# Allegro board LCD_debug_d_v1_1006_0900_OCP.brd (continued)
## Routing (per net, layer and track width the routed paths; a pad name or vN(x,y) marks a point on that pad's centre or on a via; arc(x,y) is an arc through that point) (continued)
DEBUG_V2_PRSNT: length 4.7
  TOP w0.165: v1(59.2,18.17) 57.37,18.17 R901.1 R900.2
  BOTTOM w0.165: v1(59.2,18.17) 59.03,18 U15.7
DISCHARGE_GATE: length 1.3
  TOP w0.102: Q29.G 12.43,7.65 12.82,7.26 U24.3
EEPROM_E0: length 3.8
  TOP w0.165: U16.1 60.45,5.93 60.92,5.46 R788.2 R790.2
EEPROM_E1: length 5.2
  TOP w0.165: R787.2 R791.2 58.89,6.73 59.35,7.2 U16.2
EEPROM_E2: length 6.2
  TOP w0.165: R792.1 57.18,12.73 57.18,12.09 56.98,11.89 R786.2 57.31,11.88 58.99,10.2 58.99,9.25 59.77,8.47 U16.3
FACTORY_RST: length 19.4
  TOP w0.165: R732.2 3.13,12.57 3.35,12.79 3.35,14.36 4.53,15.54 4.53,16.54 4.59,16.6 v1(4.59,16.67)
  BOTTOM w0.165: v1(4.59,16.67) 4.66,16.67 4.99,16.99 4.99,25.85 2.12,28.71 U10.22
JTAG_TI_TCK: length 39.5
  BOTTOM w0.165: J13.1 5.61,5.48 6.56,4.54 8.49,4.54 10.91,6.96 10.91,7.99 12.39,9.47 15.04,9.47 15.17,9.6 24.38,9.6 25.43,10.65 26.44,10.65 26.64,10.85 30.04,10.85 31.79,12.6 33.66,12.6 34.2,12.06 37.42,12.06 37.72,12.36 37.72,12.47 R882.1 R881.1
JTAG_TI_TCK_R: length 4.9
  TOP w0.165: U21.B15 v2(42.54,15.9)
  BOTTOM w0.165: R881.2 40.19,12.7 42.54,15.05 v2(42.54,15.9)
JTAG_TI_TDI: length 39.5
  BOTTOM w0.165: J13.2 5.28,6.49 6.75,5.01 8.29,5.01 10.44,7.16 10.44,8.19 12.2,9.94 14.85,9.94 14.99,10.08 24.2,10.08 25.23,11.12 26.24,11.12 26.44,11.32 29.84,11.32 31.59,13.07 35.43,13.07 35.57,13.21 37.44,13.21 R475.1 R474.1
JTAG_TI_TDI_R: length 6.4
  TOP w0.165: v2(42.65,17.81) 42.68,17.81 U21.D14
  BOTTOM w0.165: v2(42.65,17.81) 42.68,17.81 43.01,17.48 43.01,16.97 42.04,16 42.04,15.22 40.54,13.72 R474.2
JTAG_TI_TDO: length 47.5
  TOP w0.165: v1(5.28,4.47) 5.7,4.89 v1(5.7,7.47)
  BOTTOM w0.165: v1(5.7,7.47) 5.68,7.48 J13.3 ; v1(5.28,4.47) 5.68,4.07 8.68,4.07 11.39,6.78 11.39,7.8 12.59,9 15.23,9 15.35,9.12 24.56,9.12 25.62,10.18 26.65,10.18 26.84,10.38 30.23,10.38 31.98,12.13 33.37,12.13 33.98,11.52 38.02,11.52 38.73,12.23 40.38,12.23 42.03,13.87 R473.1
JTAG_TI_TDO_R: length 3
  TOP w0.165: U21.C14 v2(43.54,16.95)
  BOTTOM w0.165: v2(43.54,16.95) 43.54,16.38 43.09,15.93 43.09,14.7 R473.2
JTAG_TI_TMS: length 41.4
  BOTTOM w0.165: J13.4 5.5,8.49 6.21,7.78 6.21,7.21 6.05,7.06 6.05,6.38 6.95,5.48 8.1,5.48 9.97,7.35 9.97,8.38 12.01,10.41 14.65,10.41 14.81,10.57 24.02,10.57 25.04,11.59 26.05,11.59 26.25,11.79 29.65,11.79 31.4,13.54 35.16,13.54 35.85,14.22 37.44,14.22 R471.1 R469.1
JTAG_TI_TMS_R: length 4.7
  TOP w0.165: U21.C15 42.54,17.03 v2(42.21,17.36)
  BOTTOM w0.165: v2(42.21,17.36) 42.25,17.32 42.25,16.71 41.54,16 41.54,15.38 40.89,14.73 R469.2
LCD_C1M: length 3.8
  TOP w0.165: C295.2 C297.2 45.95,7.39 v1(45.35,6.78)
  BOTTOM w0.165: v1(45.35,6.78) 45.1,7.03 J4.5
LCD_C1P: length 2.6
  TOP w0.165: v1(44.6,6.79) 45.15,7.34 C297.1
  BOTTOM w0.165: J4.6 v1(44.6,6.79)
LCD_C2M: length 3.8
  TOP w0.165: v1(46.74,5.97) 46.97,5.97 C296.2
  BOTTOM w0.165: J4.3 46.1,7.34 46.74,6.7 v1(46.74,5.97)
LCD_C2P: length 3
  TOP w0.165: v1(46.01,6.45) 46.29,6.73 C296.1
  BOTTOM w0.165: v1(46.01,6.45) 46.01,6.88 45.6,7.29 J4.4
LCD_C3P: length 5.6
  TOP w0.165: C295.1 48.29,8.31 v1(48.29,8.94)
  BOTTOM w0.165: v1(48.29,8.94) 48.29,7.52 47.99,7.21 46.85,7.21 46.6,7.46 J4.2
LCD_PAGE_SKP_DOWN: length 51.4
  TOP w0.165: 9.69,8.56 9.53,8.72 9.53,9.47 8.72,10.28 8.72,10.97 8.9,11.15 8.9,11.16 9.3,11.56 11.83,11.56 v1(13.17,12.89) 13.17,14.09 R915.1 ; U21.W10 44.71,25.28 40.39,25.28 38.9,23.79 37.34,23.79 v1(36.85,24.28)
  BOTTOM w0.165: v1(13.17,12.89) 13.17,13.13 13.97,13.93 17.79,13.93 19.23,15.37 19.23,16.79 19.87,17.42 19.87,20.98 21.93,23.04 29.43,23.04 32.04,25.65 34.81,25.65 35.96,24.5 36.63,24.5 v1(36.85,24.28)
LCD_PAGE_SKP_ENTER: length 59.7
  TOP w0.165: v1(37.96,24.96) 38.18,24.74 38.73,24.74 39.68,25.69 39.97,25.81 46.51,25.81 46.56,25.86 46.92,25.86 47.17,25.61 47.17,25.07 U21.W6 ; SW6.2 6.19,13.52 6.08,13.41 6.08,12.7 6.16,12.62 v1(6.16,12.19)
  BOTTOM w0.165: v1(37.96,24.96) 36.48,26.44 31.78,26.44 30.16,24.83 21.58,24.83 18.19,21.44 18.19,17.88 16.99,16.68 16.99,15.13 16.52,14.66 13.66,14.66 12.75,13.75 12.6,13.75 11.82,12.97 8.68,12.97 7.73,12.01 6.34,12.01 v1(6.16,12.19) 5.27,11.3 5.27,9.38 6.83,7.82 R916.1
LCD_PAGE_SKP_LEFT: length 56.3
  TOP w0.165: U21.V7 45.45,25.54 40.32,25.54 39.91,25.37 38.9,24.36 v1(37.55,24.36) ; v1(6.13,11.33) 5.67,11.79 5.67,12.58 SW6.3
  BOTTOM w0.165: v1(37.55,24.36) 35.87,26.04 31.9,26.04 30.31,24.45 21.73,24.45 18.58,21.3 18.58,17.68 18.02,17.12 18.02,14.68 17.63,14.29 13.81,14.29 12.9,13.38 12.75,13.38 11.97,12.6 8.83,12.6 7.88,11.65 6.45,11.65 v1(6.13,11.33) 5.95,11.15 5.95,10.27 6.24,9.99 6.71,9.99 R914.1
LCD_PAGE_SKP_PU: length 3.5
  TOP w0.165: SW6.5 10.71,6.51 R919.2
LCD_PAGE_SKP_RIGHT: length 48.5
  TOP w0.165: R918.1 13.81,10.85 13.93,10.97 13.93,12.37 v1(13.81,12.49) 11.93,10.61 SW6.4 ; U21.R10 45.36,22.95 45.55,23.14 45.55,23.95 v2(45.52,23.97)
  BOTTOM w0.165: v2(45.52,23.97) 45.52,24.16 44.76,24.92 43.67,24.92 43.11,25.48 39.78,25.48 38.07,23.78 35.27,23.78 33.79,25.26 32.17,25.26 29.58,22.67 22.08,22.67 20.3,20.89 20.3,17.29 19.6,16.6 19.6,15.21 17.95,13.56 14.12,13.56 13.81,13.25 v1(13.81,12.49)
LCD_PAGE_SKP_UP: length 57.3
  TOP w0.165: U21.V4 47.54,24.95 47.54,25.79 46.99,26.34 44.87,26.34 44.75,26.22 39.99,26.22 39.46,26 38.78,25.32 v1(38.57,25.32) ; v1(6.44,10.48) 6.44,10.78 8.52,12.86 v1(8.52,13.83) SW6.1
  BOTTOM w0.165: v1(6.44,10.48) 6.63,10.67 R917.1 ; v1(8.52,13.83) 9.02,13.34 11.41,13.34 12.19,14.12 12.59,14.12 13.51,15.03 16.36,15.03 16.59,15.26 16.59,16.81 17.79,18.01 17.79,21.55 21.43,25.2 30.01,25.2 31.63,26.81 37.08,26.81 v1(38.57,25.32)
LCD_V0: length 4.2
  TOP w0.165: v1(46.19,10.3) 46.24,10.35 C290.1
  BOTTOM w0.165: J4.7 44.1,8.85 44.37,9.12 45.01,9.12 v1(46.19,10.3)
LCD_V1: length 4.1
  TOP w0.165: v1(45.45,10.36) 45.22,10.59 C292.1
  BOTTOM w0.165: v1(45.45,10.36) 44.9,9.82 44.39,9.82 43.6,9.03 J4.8
LCD_V2: length 3.9
  TOP w0.165: v1(44.66,10.34) 44.2,10.79 C291.1
  BOTTOM w0.165: v1(44.66,10.34) 44.51,10.19 44.18,10.19 43.1,9.11 J4.9
LCD_V3: length 3.5
  TOP w0.165: v1(43.65,10.36) 43.19,10.82 C293.1
  BOTTOM w0.165: J4.10 42.6,9.17 43.65,10.21 v1(43.65,10.36)
LCD_V4: length 3.3
  TOP w0.165: v1(42.3,9.65) 42.43,9.65 43.06,9.02 43.16,9.02 C294.1
  BOTTOM w0.165: J4.11 42.07,8.28 42.07,9.42 v1(42.3,9.65)
LCD_VLCD: length 3
  TOP w0.165: C298.1 47.04,10.95 v1(47.04,10.3)
  BOTTOM w0.165: v1(47.04,10.3) 47.1,10.24 J4.1
LCD_VREF: length 2.7
  TOP w0.165: C299.1 41.78,9.38 41.54,9.38 41.51,9.35 v1(41.47,9.35)
  BOTTOM w0.165: v1(41.47,9.35) 41.6,9.22 J4.12
LED_A1_N: length 59.4
  TOP w0.165: U21.R2 49.04,22.92 49.43,22.54 49.43,22.49 49.66,22.26 49.7,22.26 49.96,22 50.2,22 52.15,23.96 52.15,24.68 52.1,24.8 52.1,25.06 51.54,25.62 51.41,25.93 50.62,26.72 50.62,26.73 50.33,27.03 50.31,27.03 50.28,27.06 48.22,27.06 47.78,27.51 44.26,27.51 44.08,27.33 39.67,27.33 36.39,25.97 32.09,21.67 30.24,21.67 28,23.91 19.48,23.91 18.37,25.02 16.98,25.02 16.34,25.65 10.73,25.65 7.15,29.23 D6.17
LED_A2_N: length 57.9
  TOP w0.165: v1(17,23.72) 17.25,23.72 18.82,22.15 27.18,22.15 30.23,19.1 30.23,16.28 30.84,15.68 30.84,13.82 31.68,12.99 32.84,12.99 34.43,12.33 34.43,12.33 35.66,11.82 36.9,11.82 38.52,13.44 41,13.44 41.49,12.95 45.96,12.95 46.39,13.39 v1(46.39,13.47) ; v1(20.38,27.71) 19.89,28.2 17.68,28.2 17.18,28.7 15.32,28.7 14.65,29.38 D6.12 ; U21.C10 v2(44.56,16.95)
  BOTTOM w0.165: v2(44.56,16.95) 44.71,16.95 45.25,16.41 45.7,16.41 45.86,16.25 45.91,16.25 46.32,15.84 46.32,14.81 46.22,14.71 46.22,13.64 v1(46.39,13.47) ; v1(17,23.72) 17.05,23.72 17.05,23.79 18.37,25.12 19.07,25.12 20.04,26.08 20.04,27.37 v1(20.38,27.71)
LED_B1_N: length 54.9
  TOP w0.165: v1(49.86,26.2) 49.86,26.2 50.09,26.2 50.71,25.59 50.85,25.26 51.04,25.07 51.05,25.07 51.31,24.81 51.37,24.67 51.37,24.38 51.22,24.24 50.74,24.04 49.65,22.95 U21.R1 ; D6.16 8.65,29.79 12.28,26.16 16.8,26.16 17.16,25.8 18.11,25.8 19.61,24.31 28.16,24.31 30.42,22.05 31.94,22.05 36.16,26.28 39.6,27.7 43.75,27.7 43.98,27.93 47.98,27.93 48.37,27.53 49.5,27.53 v1(49.52,27.55)
  BOTTOM w0.165: v1(49.52,27.55) 49.52,26.53 49.84,26.2 v1(49.86,26.2)
LED_B2_N: length 54.1
  TOP w0.165: v1(21.09,27.71) 20.23,28.57 18.48,28.57 16.15,30.9 D6.11 ; v1(45.76,13.48) 41.55,13.48 41.14,13.89 38.45,13.89 36.75,12.19 35.74,12.19 34.64,12.64 34.64,12.64 32.91,13.35 31.94,13.35 31.21,14.09 31.21,15.99 30.74,16.46 30.74,19.3 27.48,22.57 19.09,22.57 v1(17.93,23.73) ; v2(44.02,15.97) 44.07,15.97 44.54,16.44 U21.B11
  BOTTOM w0.165: v1(21.09,27.71) 20.4,27.03 20.4,25.83 19.31,24.74 18.85,24.74 17.85,23.73 v1(17.93,23.73) ; v2(44.02,15.97) 44.05,15.94 45.66,15.94 45.95,15.65 45.95,15 45.64,14.69 45.64,13.6 v1(45.76,13.48)
LED_C1_N: length 69.3
  TOP w0.165: v1(50.79,24.62) 49.62,23.45 U21.T1 ; D6.4 7.15,18.33 7.32,18.16 8.34,18.16 8.8,17.7 9.75,17.7 11.84,15.61 14.04,15.61 14.1,15.67 14.12,15.67 15.24,16.8 17.54,16.8 18.05,17.3 22.67,17.3 23.23,16.74 23.89,16.74 25.57,15.05 25.57,13.73 26.32,12.98 26.32,11.96 27.14,11.15 28.74,11.15 29.58,10.31 31.31,10.31 31.68,9.93 34.4,9.93 35.26,9.58 38.01,9.58 38.74,10.31 42.37,10.31 43.29,9.39 47.53,9.39 48.64,10.51 48.64,14.06 50.07,15.49 50.14,15.65 50.14,17.11 51.19,18.16 51.19,18.48 v1(51.7,18.98)
  BOTTOM w0.165: v1(51.7,18.98) 52.03,18.98 53.16,20.12 53.16,20.99 52.11,22.04 52.11,22.71 51.68,23.73 v1(50.79,24.62)
LED_C2_N: length 41.2
  TOP w0.165: v1(38.77,11.43) 38.6,11.43 37.51,10.34 35.37,10.34 34.48,10.71 31.99,10.71 31.66,11.04 30.04,11.04 29.19,11.89 27.82,11.89 27.14,12.57 27.14,14.12 26.52,14.74 26.52,15.6 24.65,17.47 23.54,17.47 22.21,18.8 20.08,18.8 17.17,21.72 15.07,21.72 14.65,21.3 D6.9 ; v2(43.57,15.47) 43.66,15.56 44.24,15.56 44.54,15.86 U21.A11
  BOTTOM w0.165: v2(43.57,15.47) 43.65,15.39 43.65,13.49 43.44,13.28 42.09,13.28 40.76,11.94 40.58,11.76 38.97,11.76 38.77,11.56 v1(38.77,11.43)
LED_D1_N: length 89.6
  TOP w0.165: v1(51.08,20.12) 51.28,20.12 52.19,19.2 52.19,18.69 52.15,18.6 50.41,16.86 50.41,15.5 50.28,15.17 49.52,14.41 49.52,11.58 51.31,9.79 51.31,3.42 49.79,1.9 33.02,1.9 31.91,3.01 30.04,3.01 29.73,3.33 29.73,4.39 29.29,4.83 29.29,5.54 28.65,6.18 27.25,6.18 26.07,7.37 24.92,7.37 24.48,7.81 23.86,9.3 23.86,9.73 24.84,10.71 24.84,14.38 24.25,14.97 24.07,14.97 22.95,16.09 22.95,16.49 22.51,16.93 18.26,16.93 17.76,16.43 15.87,16.43 15.87,16.42 15.6,16.42 15.57,16.38 15.55,16.38 14.48,15.32 14.28,15.32 14.27,15.3 14.25,15.3 14.19,15.24 11.69,15.24 10.26,16.67 7.39,16.67 7.1,16.96 5.53,16.96 4.52,17.97 4.34,17.97 4.15,18.16 D6.2 ; v2(47.73,22.83) 47.84,22.83 47.91,22.91 47.94,22.91 47.97,22.94 48.07,22.94 48.08,22.95 U21.R3
  BOTTOM w0.165: v1(51.08,20.12) 50.53,20.67 50.53,22.59 50.43,22.82 50.23,23.03 49.7,23.03 49.26,22.59 47.98,22.59 v2(47.73,22.83)
LED_D2_N: length 48.1
  TOP w0.165: v2(44.92,15.14) 44.92,15.35 45.4,15.84 45.4,16.07 45.04,16.43 U21.B10 ; v1(39.81,11.25) 39.45,11.61 39.45,11.99 39.29,12.16 38.8,12.16 37.36,10.71 35.44,10.71 32.62,11.88 30.99,11.88 29.68,13.19 29.68,15.11 29.02,15.77 29.02,18.29 26.36,20.94 18.46,20.94 17.18,22.23 12.26,22.23 11.65,21.61 D6.7
  BOTTOM w0.165: v2(44.92,15.14) 44.76,14.99 44.76,13.56 43.67,12.47 42.33,12.47 41.99,12.13 41.99,11.78 41.21,11 40.14,11 39.89,11.25 v1(39.81,11.25)
LED_DP1_N: length 67.8
  TOP w0.165: v1(51.21,19.48) 50.82,19.09 50.82,18.32 49.87,17.36 49.87,15.87 49.83,15.76 48.27,14.21 48.27,10.78 47.31,9.82 43.39,9.82 42.51,10.69 38.52,10.69 37.8,9.98 35.29,9.98 34.48,10.31 31.83,10.31 31.47,10.67 29.8,10.67 28.95,11.52 27.29,11.52 26.73,12.08 26.73,13.11 25.94,13.89 25.94,15.24 24.08,17.11 23.38,17.11 22.82,17.67 17.86,17.67 17.35,17.16 15.07,17.16 13.88,15.98 12,15.98 9.86,18.11 9.2,18.11 8.65,18.66 D6.5 ; v2(48.6,23.77) 48.6,24 U21.V2
  BOTTOM w0.165: v2(48.6,23.77) 48.95,24.13 50.74,24.13 51.37,23.5 51.72,22.66 51.72,21.9 52.78,20.83 52.78,20.26 52,19.48 v1(51.21,19.48)
LED_DP2_N: length 36.9
  TOP w0.165: v1(20.83,18.3) 20.07,18.3 17.03,21.34 16.59,21.34 16.15,20.89 D6.10 ; U21.U12 v2(44.53,23.95)
  BOTTOM w0.165: v1(20.83,18.3) 20.83,20.9 22.23,22.3 29.74,22.3 31.48,24.05 33.55,24.05 34.63,22.97 38.4,22.97 40.37,24.94 42.63,24.94 43.19,24.38 43.71,24.38 44.15,23.95 v2(44.53,23.95)
LED_E1_N: length 93.8
  TOP w0.165: v2(47.12,22.94) 47.53,23.34 48.94,23.34 U21.T2 ; D6.1 2.65,18.97 4.1,17.53 4.28,17.53 4.64,17.16 4.8,17.16 5.38,16.58 6.89,16.58 7.2,16.26 10.15,16.26 11.54,14.87 14.57,14.87 15.76,16.05 16.02,16.05 16.03,16.06 18,16.06 18.49,16.55 22.27,16.55 22.58,16.24 22.58,15.86 23.86,14.58 24.02,14.58 24.41,14.2 24.41,10.89 23.43,9.91 23.43,9.39 24.19,7.55 24.77,6.97 25.95,6.97 27.1,5.82 28.46,5.82 28.89,5.38 28.89,4.7 29.34,4.24 29.34,3.19 29.89,2.64 31.76,2.64 32.87,1.53 49.94,1.53 51.67,3.27 51.67,10.03 49.89,11.82 49.89,14.26 50.6,14.97 50.78,15.4 50.78,16.71 52.51,18.44 52.57,18.58 52.57,19.53 v1(51.67,20.43)
  BOTTOM w0.165: v2(47.12,22.94) 47.44,23.25 47.91,23.25 48.22,22.94 49.14,22.94 49.6,23.39 50.41,23.39 50.72,23.08 50.92,22.61 50.92,21.18 v1(51.67,20.43)
LED_E2_N: length 48.7
  TOP w0.165: v2(44.13,15.11) 44.27,15.24 44.34,15.24 U21.A10 ; v1(41.11,11.58) 40.38,11.58 40.22,11.75 40.22,12.31 39.83,12.7 38.82,12.7 37.2,11.08 35.51,11.08 32.69,12.25 31.26,12.25 30.1,13.4 30.1,15.29 29.43,15.96 29.43,18.51 26.6,21.34 18.59,21.34 17.07,22.86 11.4,22.86 10.15,21.61 D6.6
  BOTTOM w0.165: v2(44.13,15.11) 44.13,13.45 43.59,12.91 42.25,12.91 41.11,11.77 v1(41.11,11.58)
LED_F1_N: length 62.1
  TOP w0.165: U21.P4 v2(48.56,21.93) ; v1(50.08,22.52) 50.29,22.73 50.31,22.73 51.75,24.17 51.75,24.68 51.73,24.71 51.73,24.74 51.68,24.88 51.65,24.93 51.62,25.02 51.17,25.47 51.04,25.78 50.12,26.7 47.96,26.7 47.53,27.12 44.45,27.12 44.29,26.96 39.74,26.96 36.62,25.67 32.24,21.28 30.03,21.28 27.85,23.47 19.4,23.47 18.23,24.64 16.34,24.64 15.83,25.15 8.47,25.15 4.15,29.46 D6.19
  BOTTOM w0.165: v1(50.08,22.52) 50.06,22.52 50.06,22.5 49.5,21.93 v2(48.56,21.93)
LED_F2_N: length 61.1
  TOP w0.165: D6.14 11.65,29.96 13.42,28.19 16.72,28.19 17.2,27.71 v1(19.67,27.71) ; v1(47.03,13.5) 47.03,13.41 46.59,12.97 46.5,12.97 46.11,12.59 41.33,12.59 40.85,13.07 38.67,13.07 37.05,11.45 35.59,11.45 32.76,12.62 31.52,12.62 30.47,13.67 30.47,15.49 29.85,16.1 29.85,18.77 26.91,21.71 18.74,21.71 17.22,23.23 16.67,23.23 v1(16.33,23.57) ; U21.B9 v2(45.54,16.94)
  BOTTOM w0.165: v1(16.33,23.57) 16.33,23.79 18.09,25.55 18.98,25.55 19.67,26.24 v1(19.67,27.71) ; v2(45.54,16.94) 45.97,16.51 46.26,16.51 46.69,16.08 46.69,14.66 46.59,14.56 46.59,14.02 47.03,13.58 v1(47.03,13.5)
LED_G1_N: length 58.8
  TOP w0.165: D6.20 2.65,29.44 7.58,24.51 15.58,24.51 15.82,24.27 18.08,24.27 19.34,23.01 27.74,23.01 29.88,20.88 32.6,20.88 37.24,25.53 39.82,26.59 44.55,26.59 44.7,26.74 47.4,26.74 47.81,26.33 47.82,26.33 47.86,26.29 49.08,26.29 49.72,25.65 50.13,25.65 50.4,25.38 50.48,25.17 50.28,24.68 49.55,23.95 U21.U2
LED_G2_N: length 42.3
  TOP w0.165: D6.15 10.15,30.07 13.04,27.18 17.41,27.18 19.85,24.74 v1(32.37,24.74) ; v2(44.9,23.49) 44.86,23.45 U21.T12
  BOTTOM w0.165: v1(32.37,24.74) 33.56,24.74 34.93,23.36 38.2,23.36 40.05,25.21 42.92,25.21 43.48,24.65 43.82,24.65 43.98,24.5 44.67,24.5 45.04,24.13 45.04,23.72 44.91,23.59 44.91,23.5 v2(44.9,23.49)
LED_P3V3_BT_R: length 1.5
  TOP w0.457: R12.1 4.2,1.45 D3.A
PD_EEPROM_WC: length 1.6
  TOP w0.165: U16.7 53.81,7.2 53.8,7.19 53.78,7.19 53.68,7.09 53.66,7.09 53.63,7.07 R789.1
PU_25M_BMC_CLK_EN_R: length 1.4
  TOP w0.165: OSC1.1 33.02,15.79 32.96,15.73 R51.2
PWR_BTN: length 50.5
  TOP w0.165: U21.F18 v2(40.5,18.45) ; v1(53.81,29.03) 55.85,26.99 55.85,22.54 53.94,20.63 v1(52.28,20.63)
  BOTTOM w0.165: R78.2 58.13,33.27 58.71,32.69 58.71,30.91 56.83,29.03 v1(53.81,29.03) ; v2(40.5,18.45) 40.1,18.45 39.17,17.53 39.17,17.17 38.89,16.88 37.73,16.88 37.32,17.29 37.32,20.68 37.67,21.02 37.67,21.89 37.96,22.18 38.71,22.18 40.94,24.41 42.21,24.41 43.07,23.55 44.23,23.55 44.7,23.08 45.1,23.08 45.4,23.38 45.78,23.38 45.95,23.55 48.11,23.55 48.34,23.32 49.11,23.32 49.55,23.76 50.57,23.76 51.05,23.28 51.33,22.6 51.33,21.58 v1(52.28,20.63)
PWR_BTN_R: length 13
  TOP w0.165: S1.3 54.64,35.71 57.91,35.71 v1(58.93,34.69) 58.99,34.75 59.29,34.75 60.39,33.65 S1.4
  BOTTOM w0.165: R944.1 58.93,34.47 v1(58.93,34.69) R78.1 C21.2
PWRGD_P3V3: length 15.7
  TOP w0.165: U12.5 38.96,6.66 39.13,6.83 39.13,7.06 R808.1 38.17,8.07 38.84,8.75 39.95,9.86 40.67,9.86 40.98,9.55 40.98,9.14 42.12,7.99 42.12,7.13 R903.1 43.27,6.62 44.17,5.72 Q14.G Q13.G
PWRGD_P3V3_BAT: length 1.2
  TOP w0.165: PR38.2 19.74,13.68 PU1.8
Q21_G: length 2.9
  TOP w0.165: Q21.G 30.5,4.44 29.78,5.15 R905.1 R906.1
REV_ID_0: length 5.3
  TOP w0.165: U21.G19 39.63,18.95 39.28,19.3 R920.1 R921.2
REV_ID_1: length 6.4
  TOP w0.165: U21.H18 39.41,21.08 37.32,21.08 37.07,21.34 R923.2 R922.1
RST_BTN: length 42.7
  TOP w0.165: U21.C6 47.49,17.4 48,17.4 v2(48.02,17.41) ; v1(50.17,18.31) 50.41,18.55 50.41,20.14 51.48,21.21 53.93,21.21 55.43,22.71 55.43,26.43 53.24,28.62 53.24,30.79 52.23,31.8 51.18,31.8 50.23,32.75 47.59,32.75 46.67,33.66 43.85,33.66 43.26,33.07 41.63,33.07 41.37,32.81 41.29,32.78 38.07,32.78 36.52,31.23 R725.2
  BOTTOM w0.165: v2(48.02,17.41) 48.61,17.41 49.15,17.95 49.15,18.09 49.47,18.41 50.07,18.41 v1(50.17,18.31)
RST_BTN_R: length 21.5
  TOP w0.165: R910.1 29.49,31.69 29.8,32 30.82,32 C244.2 R725.1 32.83,31.48 33.46,32.11 36.66,32.11 37.78,33.22 39.28,33.22 39.7,33.65 S2.3 42.13,33.65 42.25,33.53 43.12,33.53 43.67,34.08 47.15,34.08 47.59,33.65 S2.4
RST_LCD_N: length 22.2
  TOP w0.165: v2(42.07,17.95) U21.E17 ; v1(29.36,12.38) 30.28,11.46 32.16,11.46 v1(32.44,11.18)
  BOTTOM w0.165: v1(29.36,12.38) 29.58,12.38 31.2,14.01 34.89,14.01 36.36,15.47 38.62,15.47 40.01,16.87 40.01,17.07 40.42,17.48 40.93,17.48 41.4,17.95 v2(42.07,17.95) ; J4.30 32.6,11.02 v1(32.44,11.18)
RST_N: length 3.8
  BOTTOM w0.165: U10.5 16.44,26.31 16.47,26.29 C252.1 R730.2
S3_A2: length 15
  TOP w0.165: S3.2 20.1,5.41 v1(20.24,5.55)
  BOTTOM w0.165: Q31.G 31.2,17.62 Q32.G 30.38,17.87 30.22,18.03 26.53,18.03 25.43,16.94 25.43,15.95 23.25,13.77 v1(21.12,13.77)
S3_A3: length 3.4
  TOP w0.165: S3.3 21.6,5.03 23.01,6.44 D17.3
SEG_SEL_1: length 17.9
  TOP w0.457: v1(5.7,17.49) R758.1 6.42,17.8 5.65,18.56 D6.3 ; D6.18 v1(5.65,30)
  BOTTOM w0.457: v1(5.65,30) 5.65,17.53 v1(5.7,17.49)
SEG_SEL_2: length 18.1
  TOP w0.457: D6.8 13.15,17.55 13.21,17.49 R759.1 v1(12.3,17.48) ; D6.13 v1(13.15,30)
  BOTTOM w0.457: v1(13.15,30) 12.3,29.15 v1(12.3,17.48)
SET_BAUD_RATE: length 3.1
  BOTTOM w0.165: R10.2 16.78,27.51 U10.4
SET_BT_MASTER: length 3
  BOTTOM w0.165: R11.2 16.97,28.71 U10.3
SET_BT_MODE: length 17.4
  TOP w0.165: v1(3.59,16.53) 3.9,16.21 3.9,15.47 2.98,14.55 2.98,13.07 R2.2
  BOTTOM w0.165: v1(3.59,16.53) 3.63,16.58 3.63,17.11 4.12,17.6 4.12,25.17 2.99,26.3 2.13,26.3 2.12,26.31 U10.20
SMB_SCL: length 22.1
  TOP w0.165: v1(47.2,14.92) 47.14,14.92 46.87,14.64 42.02,14.64 41.54,15.12 U21.A17 ; U16.6 54.48,8.47 54.04,8.91 50.48,12.47 v1(50.48,13.84) 51.11,14.48 51.11,14.68 51.7,15.27 52.06,15.42 R926.2
  BOTTOM w0.165: v1(50.48,13.84) 47.67,13.84 47.26,14.26 47.26,14.85 v1(47.2,14.92)
SMB_SCL_R: length 14
  TOP w0.165: v1(59.22,21.54) 58.5,20.83 58.5,19.12 58.89,18.73 59.51,18.73 59.72,18.52 59.72,17.84 59.56,17.68 58.1,17.68 55.81,15.38 54.78,15.38 54.74,15.42 R926.1 R925.2
  BOTTOM w0.165: v1(59.22,21.54) 58.99,21.54 58.53,22 U15.5
SMB_SDA: length 22.8
  TOP w0.165: U16.5 54.68,9.8 54.68,9.97 54.27,10.39 54.27,11.76 R927.2 51.8,12.37 51.19,12.98 v1(51.19,13.84) ; v1(47.83,14.89) 47.83,14.82 47.83,14.82 47.83,14.79 47.11,14.07 41.77,14.07 41.31,14.53 40.57,14.53 39.78,15.32 v1(39.78,15.47) ; v2(41.82,16.89) 41.82,16.72 U21.B17
  BOTTOM w0.165: v2(41.82,16.89) 41.21,16.89 v1(39.78,15.47) ; v1(51.19,13.84) 50.53,14.5 48.22,14.5 v1(47.83,14.89)
SMB_SDA_R: length 13.2
  TOP w0.165: R927.1 R924.2 54.59,13.51 54.59,13.64 54.9,13.95 54.9,14.73 55.18,15.01 55.96,15.01 58.24,17.3 59.75,17.3 60.09,17.64 v1(60.09,18.99)
  BOTTOM w0.165: U15.6 58.57,20 59.58,18.99 v1(60.09,18.99)
SPI_BMC_LCD_CS_N: length 29.1
  BOTTOM w0.165: J4.19 38.1,7.63 38.69,7.04 39.05,6.16 39.19,6.02 39.94,6.02 40.63,6.71 43.71,6.71 47.58,4.53 49.74,4.53 49.96,4.74 49.96,6.52 48.85,7.62 48.85,9.7 52.85,13.7 52.85,15.96 51.93,16.89 R79.2
SPI_BMC_LCD_CS_N_R: length 2.5
  TOP w0.165: v1(49.64,17.96) 49.63,17.95 U21.E2
  BOTTOM w0.165: R79.1 50.99,17.04 50.45,17.58 50.02,17.58 v1(49.64,17.96)
SPI_BMC_LCD_SCK: length 31.6
  BOTTOM w0.165: R516.2 49.89,16.5 50.05,16.33 51.62,16.33 52.31,15.65 52.31,14.05 51.52,13.26 48.32,13.26 48.09,13.03 48.09,11.1 47.91,10.92 47.62,10.92 47.46,11.09 47.46,11.98 47.3,12.14 47.07,12.14 46.9,11.98 46.9,11.09 46.74,10.92 46.51,10.92 46.34,11.09 46.34,11.98 46.18,12.14 45.95,12.14 45.78,11.98 45.78,11.09 45.62,10.92 45.39,10.92 45.23,11.09 45.23,11.98 45.06,12.14 44.83,12.14 44.67,11.98 44.67,11.09 44.5,10.92 42.78,10.92 41.82,9.96 39.72,9.96 39.48,10.2 38.21,10.2 37.91,10.5 37.12,10.5 36.6,9.99 J4.22
SPI_BMC_LCD_SCK_R: length 1.9
  TOP w0.165: v2(48.31,16.9) 48.54,17.14 U21.E3
  BOTTOM w0.165: R516.1 48.32,16.89 v2(48.31,16.9)
SPI_BMC_LCD_SDI: length 32
  BOTTOM w0.165: R513.2 53.4,16.3 53.4,13.44 49.44,9.47 49.44,7.87 50.5,6.81 50.5,4.51 49.96,3.96 47.44,3.96 43.58,6.12 40.89,6.12 40.38,5.61 39.97,5.44 38.89,5.44 38.59,5.75 38.01,7.13 37.6,7.54 J4.20
SPI_BMC_LCD_SDI_R: length 5.3
  TOP w0.165: U21.H4 48.04,20.48 v2(48.07,20.51)
  BOTTOM w0.165: R513.1 50.99,18.21 50.33,18.87 49.97,18.87 48.59,20.25 48.33,20.25 v2(48.07,20.51)
SPI_BMC_LCD_SDO: length 38
  BOTTOM w0.165: J4.21 37.1,7.44 37.27,6.57 37.98,5.51 38.61,4.88 40.38,4.88 40.47,4.92 41.04,5.49 43.56,5.49 47.19,3.4 50.05,3.4 50.31,3.51 51.05,4.25 51.05,7.07 50,8.13 50,9.09 53.94,13.04 53.94,16.57 52.12,18.39 51.59,18.39 50.12,19.86 49.93,20.31 49.93,20.78 R72.2
SPI_BMC_LCD_SDO_R: length 1.4
  TOP w0.165: v2(48.57,20.93) 48.56,20.93 U21.M4
  BOTTOM w0.165: v2(48.57,20.93) 48.65,20.85 R72.1
SUPPLY_INPUT: length 8.2
  TOP w0.165: v1(13.75,2.15) 13.75,2.82 13.45,3.12 13.45,3.75 12.96,4.25 12.96,4.7 13.32,5.06 U24.5
  BOTTOM w0.165: R941.1 C336.1 11.24,1.49 11.49,1.24 12.85,1.24 v1(13.75,2.15)
UART_CH_SEL: length 17.1
  TOP w0.165: SW5.3 28.83,34.1 35.87,34.1 SW5.4 38.26,33.65 39.34,34.73 v1(39.85,34.73)
  BOTTOM w0.165: R888.1 40.1,37.23 40.32,37 40.8,37 C332.2 R880.2 41.35,35.07 41.01,34.73 v1(39.85,34.73)
UART_CH_SEL_BIC: length 51.5
  TOP w0.165: v2(42.53,18.39) 42.47,18.45 U21.F16 ; v1(28.41,27.69) 31.05,27.69 31.78,26.95 33.58,26.95 34.09,26.44 34.09,24.91 v1(31.81,22.63) ; v1(27.42,31.73) 26.97,32.19 26.97,34.74 28.06,35.83 36.14,35.83 38.36,38.05 v1(38.36,38.2)
  BOTTOM w0.165: v1(27.42,31.73) 27.49,31.67 27.49,28.38 28.18,27.69 v1(28.41,27.69) ; v1(31.81,22.63) 32.8,21.64 33.2,20.69 33.51,19.93 34.31,19.13 34.89,18.9 35.08,18.82 35.39,18.69 36.66,18.16 36.95,17.87 36.95,16.88 37.31,16.52 39.06,16.52 39.56,17.01 39.56,17.25 40.24,17.93 40.8,17.93 41.31,18.45 42.47,18.45 v2(42.53,18.39) ; v1(38.36,38.2) 38.63,37.93 40.63,37.93 40.9,37.66 R888.2 R912.1
UART_CTS: length 7.7
  TOP w0.165: R731.2 3.07,16.25 v1(3.07,16.92)
  BOTTOM w0.165: v1(3.07,16.92) 3.07,17.09 3.74,17.76 3.74,19.96 2.21,21.5 2.13,21.5 2.12,21.51 U10.16
UART_GATE: length 4.2
  BOTTOM w0.165: R358.1 R357.2 42.02,30.51 42.5,30.99 Q5.5 Q5.2
UART_RTS: length 6
  TOP w0.165: v1(3.06,17.86) 3.06,17.6 2.57,17.12 2.57,16.58 2.64,16.51 R731.1
  BOTTOM w0.165: v1(3.06,17.86) 2.98,17.86 2.75,18.08 2.75,19.81 2.26,20.3 2.13,20.3 2.12,20.31 U10.15
UART_TI_R_RXD: length 6.5
  TOP w0.165: U21.J1 49.87,20.28 49.87,20.97 53.52,24.62 R871.1
UART_TI_R_TXD: length 6.7
  TOP w0.165: R870.1 53.23,23.64 50.14,20.55 50.14,20.08 49.68,19.62 49.35,19.62 49.04,19.93 U21.J2
UART_TI_RXD: length 43.9
  TOP w0.165: R871.2 51.19,27.91 51.19,29.74 50.71,30.23 49.06,30.23 48.57,29.74 42.73,29.74 42.3,30.18 40.05,30.18 38.78,31.45 38.09,31.45 36.83,30.19 30.02,30.19 29.8,29.97 27.72,29.97 25.08,32.61 20.47,32.61 17.9,35.18 v1(17.69,35.18)
  BOTTOM w0.165: CN1.3 v1(17.69,35.18)
UART_TI_TXD: length 47.6
  TOP w0.165: R870.2 54.2,23.36 54.2,25.79 51.67,28.32 51.67,29.92 51.66,29.93 51.66,29.94 50.89,30.71 48.77,30.71 48.45,30.38 43.59,30.38 42.99,30.98 42.5,30.98 42.22,30.71 40.18,30.71 38.96,31.93 37.91,31.93 36.69,30.71 29.55,30.71 29.37,30.53 27.83,30.53 25.28,33.08 20.66,33.08 v1(17.75,35.99)
  BOTTOM w0.165: CN1.2 17.91,35.83 v1(17.75,35.99)
USB2_DN: length 37.1
  TOP w0.152: J1.2 32.33,28.87 32.18,28.72 32.18,28.25 32.5,27.93 37.68,27.93 39.1,28.52 39.71,29.13 40.53,29.46 41.99,29.46 42.48,28.98 48.28,28.98 48.76,28.5 49.74,28.5 49.91,28.68 49.91,29.31 v1(49.67,29.55)
  BOTTOM w0.152: U15.2 56.8,17 56.22,17.58 56.22,17.99 55.46,18.75 54.75,20.47 54.53,21.68 52.87,24.32 52.02,24.93 51.8,25.09 51.8,25.1 51.46,25.21 50.58,26.09 50.58,27.21 49.91,28.81 49.91,29.31 v1(49.67,29.55)
USB2_DN_MICRO: length 15.7
  BOTTOM w0.152: J2.2 50.7,36.99 50.99,36.7 50.99,36.6 50.87,36.48 49.71,36 49.19,36 49.06,36.13 48.6,36.13 48.48,36 48.02,36 47.19,35.17 47.19,28.75 47.06,28.62 47.06,28.17 47.19,28.04 47.19,27.52 47.04,27.37 46.86,27.37 46.55,27.06 46.55,26.89 46.21,26.54 46.08,26.54 45.95,26.67 U5.16
USB2_DP: length 37
  TOP w0.152: v1(50.43,29.55) 50.19,29.31 50.19,28.56 49.85,28.22 48.65,28.22 48.17,28.7 42.36,28.7 41.88,29.18 40.58,29.18 39.87,28.89 39.26,28.28 37.73,27.65 32.38,27.65 31.9,28.14 31.9,28.72 31.74,28.87 J1.3
  BOTTOM w0.152: U15.3 56.78,19 56.3,18.52 56.08,18.52 55.7,18.91 55.02,20.55 54.8,21.79 53.08,24.51 52.18,25.15 51.97,25.32 51.93,25.35 51.61,25.45 50.86,26.2 50.86,27.26 50.19,28.87 50.19,29.31 v1(50.43,29.55)
USB2_DP_MICRO: length 15.8
  BOTTOM w0.152: U5.15 45.82,26.02 46.06,26.26 46.33,26.26 47.15,27.09 47.15,27.09 47.47,27.41 47.47,35.05 48.14,35.72 49.76,35.72 51.03,36.25 51.27,36.48 51.27,36.78 51.35,36.87 J2.3
VOLTAGE_SENSE: length 1.9
  TOP w0.165: R942.2 14.85,6.84 13.82,5.81 U24.6
N17920453:
  vias: v1(60.28,37.08) v1(60.28,36.45) v1(60.28,35.79) v1(60.94,37.08) v1(60.94,36.45) v1(60.94,35.79)
N17920501: length 9.3
  TOP w0.165: S2.2 46.77,38.15 46.64,38.02 46.06,38.02 v1(45.85,37.82) 45.53,38.15 S2.1
  BOTTOM w0.165: v1(45.85,37.82) 45.85,38.13 45.5,38.48 R724.2
N18231426: length 14.6
  TOP w0.165: SW5.1 SW5.2 v1(37.5,38.15)
  BOTTOM w0.165: v1(37.5,38.15) 38.44,39.09 40.52,39.09 40.9,38.72 R911.2 R913.1
N18364174: length 1.5
  TOP w0.165: PC3.1 20.76,14.45 20.24,13.93 PU1.7
N18390536: length 32.6
  TOP w0.165: D15.A 7.45,2.41 v1(7.45,5.97)
  BOTTOM w0.165: R930.1 26.02,21.13 22.66,21.13 22.11,20.57 22.11,17.32 20.79,16 20.79,14.73 18.43,12.38 15.43,12.38 14.31,11.25 11.66,11.25 9.13,8.73 9.13,7.94 7.45,6.25 v1(7.45,5.97)
N18393594: length 1.1
  BOTTOM w0.165: C329.1 28.04,15.05 R895.2

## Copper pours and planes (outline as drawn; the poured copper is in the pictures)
GND on TOP (solid shape): 37.98,7.06 37.98,2.69 37.93,2.64 36.89,2.64 36.74,2.79 36.74,4.11 36.58,4.27 36.23,4.27 36.2,4.29 36.2,7.09 36.25,7.14 37.9,7.14
GND on TOP (solid shape): 32.73,6.35 32.75,6.3 32.7,5.3 32.7,3.94 32.6,3.84 31.33,3.84 31.25,3.91 31.25,5.83 31.36,5.94 31.37,5.94 31.87,6.45 31.87,6.58 31.91,6.67 32,6.71 32.37,6.71
GND on TOP (solid shape): 0.51,9.39 0.66,9.62 0.94,9.57 1.01,9.49 1.01,3.25 0.95,3.14 0.82,3.14 0.81,3.15 0.62,3.15 0.51,3.26
GND on TOP (solid shape): 19.39,13.89 19.39,13.21 19.52,13.08 20.79,13.08 20.94,13.23 21.32,13.23 21.42,13.13 21.42,12.83 21.24,12.65 20.2,12.65 19.84,12.3 19.84,11.89 19.77,11.81 19.52,11.81 19.34,11.63 19.34,11.1 19.31,11.07 19.16,11.07 19.13,11.1 19.13,11.84 19.19,11.89 19.19,12.88 19.13,12.93 19.13,13.97 19.16,14 19.29,14
GND on TOP (solid shape): 4,0.97 4.82,0.97 4.87,0.92 5.93,0.92 5.93,0.94 6.01,1.01 11.42,1.01 11.67,0.76 14.59,0.76 14.59,0.51 2.29,0.51 2.23,0.58 2.19,0.67 2.23,0.76 2.25,0.78 2.28,0.79 2.41,0.86 2.52,0.96 2.57,1 2.62,1.01 3.96,1.01
GND on TOP (solid shape): 23.72,14.24 23.88,14.24 24.07,14.06 24.07,11.68 24,11.51 23.82,11.43 23.61,11.36 23.48,11.18 23.47,11.16 23.23,10.92 22.59,10.92 22.54,10.97 22.54,11.55 23.05,12.06 23.05,12.09 23.07,12.12 23.07,14.21 23.19,14.33 23.64,14.33
GND on TOP (solid shape): 61.87,22.48 61.95,22.44 61.99,22.35 61.99,22.28 61.93,22.22 61.93,21.69 61.99,21.63 61.99,13.06 61.84,12.83 61.56,12.88 61.49,12.95 61.49,16.5 61.65,16.66 61.65,21.59 61.49,21.75 61.49,22.21 61.51,22.29 61.59,22.34 61.69,22.37 61.77,22.44 61.79,22.46 61.84,22.48
GND on TOP (solid shape): 61.56,11.3 61.84,11.35 61.99,11.12 61.99,2.08 61.82,1.91 61.82,1.63 61.78,1.54 61.69,1.5 61.55,1.5 61.46,1.54 61.42,1.63 61.42,1.65 61.43,1.67 61.47,1.83 61.49,2 61.49,9.13 61.5,9.15 61.53,9.3 61.5,9.45 61.49,9.47 61.49,11.23
GND on TOP (solid shape): 56.62,41.17 56.7,41.13 56.74,41.04 56.74,40.5 57.04,39.79 57.75,39.49 61.5,39.49 61.85,39.35 61.99,39 61.99,30.73 61.95,30.64 61.87,30.6 61.61,30.6 61.52,30.64 61.49,30.73 61.49,34.5 61.5,34.54 61.52,34.58 61.61,34.82 61.52,35.06 61.5,35.1 61.49,35.15 61.49,35.31 61.5,35.36 61.52,35.4 61.61,35.64 61.52,35.88 61.5,35.92 61.49,35.96 61.49,36.16 61.5,36.19 61.55,36.37 61.5,36.55 61.49,36.58 61.49,36.82 61.5,36.85 61.55,37.03 61.5,37.21 61.49,37.24 61.49,38.99 57.75,38.99 56.95,39.22 56.39,39.84 56.39,41.13 56.42,41.17
GND on TOP (solid shape): 38.84,40.61 38.89,40.61 38.93,40.58 39.02,40.49 39.02,40.21 38.92,40.11 25.45,40.11 24.91,39.3 23.99,38.99 19.21,38.99 19.11,39.09 18.15,39.09 18.04,38.99 17.65,38.99 16.95,38.7 16.66,38 16.66,36.1 16.45,35.32 15.86,34.76 15.86,34.5 15.63,34.26 14.84,34.26 14.52,34.59 4.71,34.59 4.39,34.26 3.17,34.26 2.85,34.59 2,34.59 1.3,34.3 1.01,33.6 1.01,17.36 0.99,17.33 0.92,17.11 0.99,16.89 1.01,16.86 1.01,14.09 0.94,14.01 0.66,13.96 0.51,14.19 0.51,33.6 0.94,34.65 2,35.09 15.15,35.09 15.86,35.39 16.16,36.1 16.16,38 16.59,39.05 17.65,39.49 23.99,39.49 24.7,39.78 24.99,40.49 24.99,40.54 25.07,40.61
GND on BOTTOM (solid shape): 32.44,6.5 32.44,4.93 32.27,4.75 30.21,4.75 30.06,4.9 30.06,6.1 30.59,6.63 32.32,6.63
GND on BOTTOM (solid shape): 43.34,23.29 43.34,22.86 43.34,22.83 42.73,22.23 42.35,22.23 42.32,22.25 42.32,22.44 42.8,22.92 42.8,23.24 42.87,23.31 43.32,23.31
GND on BOTTOM (solid shape): 47.43,19.86 47.43,18.36 47.38,18.31 46.82,18.31 46.57,18.57 46.57,19.81 46.6,19.9 46.69,19.94 47.35,19.94
GND on BOTTOM (solid shape): 7.93,11.06 8.02,11.03 8.06,10.94 8.06,8.66 7.71,8.31 6.82,8.31 5.75,9.38 5.72,9.42 5.71,9.47 5.71,9.62 5.83,9.74 5.92,9.78 6.01,9.74 6.1,9.65 6.31,9.65 6.73,9.23 7.28,9.23 7.31,9.27 7.41,9.27 7.41,9.36 7.44,9.4 7.44,11 7.51,11.06
GND on BOTTOM (solid shape): 56.12,40.7 56.21,40.66 56.25,40.57 56.25,40.5 56.25,40.39 56.27,40.26 56.27,38.13 55.99,37.85 53.42,37.85 53.12,37.54 53.12,36.96 52.92,36.75 52.59,36.75 52.43,36.91 52.43,38.28 52.36,38.35 49.69,38.35 49.06,37.72 46.59,37.72 46.44,37.87 46.44,38.57 46.45,38.59 46.49,38.79 46.45,38.98 46.44,39 46.44,40.46 46.68,40.7
GND on BOTTOM (solid shape): 61.6,10.77 61.69,10.73 61.73,10.64 61.73,8.33 61.69,8.24 61.6,8.2 57.38,8.2 57.34,8.25 56.33,8.25 56.27,8.27 56.22,8.32 56.21,8.35 56.21,8.42 56.22,8.43 56.22,8.56 56.25,8.65 56.34,8.69 57.13,8.69 57.41,8.97 57.41,10.57 57.62,10.77
GND on BOTTOM (solid shape): 61.15,3.89 61.15,3 61.07,2.82 60.9,2.74 60.54,2.36 60.9,1.98 61.07,1.9 61.15,1.73 61.15,1.3 61.13,1.24 61.09,1.2 60.95,1.11 60.78,1.04 57.49,1.04 57.36,1.17 57.36,3.96 57.44,4.04 60.99,4.04
GND on BOTTOM (solid shape): 46.74,23.01 46.74,22.73 46.92,22.56 47.51,22.56 47.58,22.48 47.58,22.14 47.53,22.09 47.04,22.09 46.92,21.97 46.92,21.68 46.32,21.08 45.77,21.08 45.37,20.69 45.37,20.08 45.33,20.04 43.91,20.04 43.67,19.8 43.67,19.33 43.73,19.23 43.75,19.18 43.73,19.12 43.67,19.02 43.61,18.95 43.29,18.95 42.91,19.33 42.91,19.66 42.76,19.81 42.38,19.81 42.35,19.84 42.35,20.37 43.62,20.37 43.85,20.6 44.51,20.6 44.81,20.9 44.81,21.3 44.78,21.45 44.7,21.57 44.42,21.86 44.41,22.02 44.56,22.06 44.65,22.02 45.41,22.02 45.54,22.09 45.8,22.35 45.8,23.06 45.85,23.11 46.64,23.11
GND on BOTTOM (solid shape): 0.89,15.11 0.98,15.08 1.01,14.99 1.01,10.62 1.02,10.62 1.23,10.41 2.85,10.41 2.9,10.36 2.9,9.25 2.83,9.17 1.56,9.17 1.28,8.89 1.28,5.03 1.51,4.8 2.75,4.8 2.95,4.6 2.95,3.53 2.83,3.4 1.2,3.4 1.01,3.22 1.01,2 1.18,1.45 1.63,1.08 1.67,1.06 1.7,1.03 1.73,0.98 1.77,0.93 1.9,0.8 1.93,0.66 1.81,0.59 1.68,0.59 1.52,0.75 1.27,0.75 0.79,1.22 0.79,1.28 0.66,1.41 0.66,1.54 0.57,1.63 0.57,1.8 0.52,1.85 0.52,1.95 0.51,1.96 0.51,2 0.51,14.99 0.55,15.08 0.63,15.11
GND on BOTTOM (solid shape): 61.93,22.17 61.93,21.7 61.99,21.64 61.99,2 61.56,0.94 60.5,0.51 57.06,0.51 56.82,0.66 56.88,0.94 56.95,1.01 60.5,1.01 61.2,1.3 61.49,2 61.49,9.1 61.53,9.3 61.5,9.45 61.49,9.47 61.49,10 61.04,10.44 61.04,10.69 61.17,10.82 61.17,10.92 61.02,11.07 58.38,11.07 58.15,11.3 58.15,13.11 58.35,13.31 60.56,13.31 61.49,14.24 61.71,14.47 61.71,16.93 61.49,17.15 61.49,18.69 61.51,18.71 61.51,22.18 61.63,22.3 61.81,22.3
GND on BOTTOM (solid shape): 38.64,40.54 38.79,40.54 38.9,40.44 38.9,40.28 38.72,40.11 25.45,40.11 24.91,39.3 23.99,38.99 19.14,38.99 19.03,39.09 18.22,39.09 18.12,38.99 17.65,38.99 16.95,38.7 16.66,38 16.66,36.1 16.66,36.04 16.16,36.04 16.16,36.1 16.16,38 16.59,39.05 17.65,39.49 23.99,39.49 24.7,39.78 25.03,40.58 25.12,40.61 38.57,40.61
GND on GND (solid shape): outline of 1291 points within 0.51,0.51 61.99,41.19
GND on VCC (solid shape): 45.11,37.13 45.11,30.3 44.07,29.27 41.53,29.27 41.17,28.91 41.17,28.64 41.12,28.57 41.08,28.56 40.85,28.37 40.82,28.08 40.78,27.85 40.57,27.75 37.76,27.75 37.23,28.27 37.23,33.07 38.14,33.97 41.31,33.97 41.83,34.46 41.83,36.37 42.17,36.73 42.21,36.76 42.26,36.77 42.58,36.77 43.04,37.22 43.23,37.3 43.41,37.21 43.76,37.09 44.05,37.32 44.1,37.38 44.17,37.4 44.84,37.4
GND on VCC (solid shape): 18.67,36.39 20.96,36.39 21.74,35.61 21.74,33.99 19.06,31.31 17.94,31.31 16.04,33.21 5.09,33.21 3.58,31.7 3.58,16.97 3.53,16.91 3.48,16.9 3.26,16.72 3.21,16.44 3.21,16.38 3.18,16.32 2.93,16.07 1.14,16.07 1.05,16.1 1.02,16.19 1.02,31.58 1.02,31.63 1.05,31.67 1.15,31.93 1.05,32.19 1.02,32.23 1.02,32.27 1.02,33.6 1.3,34.3 2,34.58 14.9,34.58 14.95,34.57 14.99,34.54 15.32,34.42 15.61,34.62 15.64,34.66 15.68,34.68 16.33,35.15 16.65,35.9 16.8,36.16 16.7,36.45 16.67,36.49 16.67,36.54 16.67,36.64 16.7,36.73 16.79,36.77 18.29,36.77
GND on VCC (solid shape): outline of 373 points within 3.7,2.98 60.47,38.29
P3V3_BAT on TOP (solid shape): 21.98,15.09 22.17,15.01 22.23,14.81 22.32,14.54 22.57,14.4 22.73,14.32 22.79,14.15 22.79,12.17 22.28,11.66 22.28,10.62 22,10.34 20.41,10.34 20.36,10.35 20.32,10.38 20.13,10.57 20.13,11.64 20.12,11.64 20.1,11.69 20.1,12.19 20.3,12.4 20.58,12.4 20.64,12.39 21.14,12.39 21.15,12.4 21.35,12.4 21.67,12.72 21.67,13.24 21.44,13.47 21.43,13.55 21.45,13.59 21.5,13.78 21.44,13.97 21.42,14 21.42,14.78 21.72,15.09
P3V3_BIC on TOP (solid shape): 38.87,9.47 38.87,9.26 38.71,9.09 38.25,8.64 37.98,8.64 36.9,7.56 36.14,7.56 35.62,7.04 34.68,7.04 34.55,7.16 34.55,7.95 33.74,8.76 33.74,9.37 33.92,9.55 34.44,9.55 34.89,9.36 35.01,9.25 35.18,9.25 35.19,9.24 38.15,9.24 38.58,9.68 38.67,9.68
P3V3_BIC on TOP (solid shape): 39.51,39.67 39.78,39.54 40.09,39.49 44.95,39.49 45.24,39.53 45.5,39.65 45.53,39.67 45.91,39.67 46.31,39.27 46.31,39.12 46.36,39.07 46.36,38.71 46.24,38.58 41.82,38.58 41.49,38.91 41.38,38.91 41.38,38.94 39.57,38.94 39.57,38.75 39.1,38.28 39,38.28 38.79,38.48 38.79,39.57 38.9,39.67
P3V3_BIC on TOP (solid shape): 39.37,5.51 39.59,5.51 39.91,5.18 40.39,5.18 40.59,5.09 40.65,4.89 40.64,4.83 40.64,4.38 40.91,4.11 40.91,3.94 40.95,3.75 41.05,3.6 41.38,3.26 41.38,2.67 41.26,2.54 38.34,2.54 38.24,2.64 38.24,5.66 38.27,5.75 38.36,5.79 39.08,5.79
P3V3_BIC on BOTTOM (solid shape): 48.75,19.71 48.75,18.03 48.65,17.93 48.61,17.9 48.56,17.89 48.49,17.89 48.38,17.78 47.84,17.78 47.68,17.93 47.68,19.72 47.77,19.91 47.98,19.97 48.06,19.96 48.14,19.98 48.16,19.98 48.48,19.98
P3V3_BIC on BOTTOM (solid shape): 39.58,9.62 39.76,9.62 39.95,9.54 40.11,9.06 40.39,8.94 40.54,8.94 40.68,8.8 40.71,8.76 40.72,8.71 40.72,8.25 40.72,8.19 40.72,7.17 40.69,7.08 40.6,7.04 40.49,7.04 39.88,6.44 39.52,6.44 39.38,6.58 39.38,9.04 39.34,9.08 38.45,9.08 38.31,9.22 38.31,9.55 38.39,9.63 39.58,9.63
P3V3_BIC on BOTTOM (solid shape): 35.72,21.34 35.72,19.41 35.54,19.23 34.96,19.23 34.5,19.42 33.94,19.98 33.94,20.32 34.5,20.32 34.5,20.26 34.52,20.21 34.54,20.16 34.56,20.11 34.6,20.07 34.64,20.03 34.68,19.99 34.73,19.97 34.79,19.95 34.84,19.94 34.9,19.94 34.95,19.94 35.01,19.96 35.06,19.98 35.1,20.01 35.15,20.04 35.18,20.09 35.22,20.13 35.24,20.18 35.25,20.24 35.26,20.29 35.26,20.35 35.25,20.4 35.24,20.46 35.22,20.51 35.18,20.55 35.15,20.6 35.1,20.63 35.06,20.66 35.01,20.68 34.95,20.7 34.9,20.7 34.84,20.7 34.79,20.69 34.73,20.67 34.68,20.65 34.64,20.61 34.6,20.57 34.56,20.53 34.54,20.48 34.52,20.43 34.5,20.38 34.5,20.32 33.94,20.32 33.94,21.44 34.09,21.59 35.47,21.59
P3V3_BIC on BOTTOM (solid shape): 44.16,23.24 44.16,22.9 44.2,22.85 45.27,22.85 45.31,22.9 45.51,22.9 45.55,22.87 45.55,22.45 45.39,22.3 45.35,22.28 44.7,22.28 44.68,22.29 44.2,22.17 44.24,21.68 44.52,21.39 44.55,21.35 44.56,21.3 44.56,21.01 44.41,20.85 43.75,20.85 43.52,20.62 41.54,20.62 41.44,20.73 41.44,21.34 42.08,21.98 42.82,21.98 43.62,22.78 43.62,23.24 43.68,23.3 44.1,23.3
P3V3_BIC on BOTTOM (solid shape): 47.89,21.69 47.89,20.83 47.87,20.78 47.84,20.76 47.76,20.64 47.73,20.5 47.69,20.39 47.69,20.28 47.68,20.22 47.65,20.18 47.61,20.14 47.51,20.14 47.46,20.19 46.39,20.19 46.31,20.12 46.31,19.95 46.31,19.93 46.29,19.81 46.31,19.7 46.31,19.68 46.31,19.22 46.31,19.18 46.31,17.98 46.63,17.67 46.63,16.92 46.55,16.81 46.41,16.84 46.4,16.85 46.11,16.85 46.03,16.93 46.03,17.25 45.75,17.53 45.75,18.47 45.63,18.59 44.84,18.59 44.71,18.72 44.15,18.72 43.97,18.9 43.97,18.98 44.03,19.18 43.97,19.38 43.95,19.41 43.95,19.68 44.03,19.76 45.45,19.76 45.65,19.96 45.65,20.57 45.88,20.8 46.44,20.8 46.56,20.92 46.64,20.92 46.64,21.01 47.02,21.39 47.02,21.63 47.02,21.69 47.12,21.79 47.79,21.79
P3V3_BIC on BOTTOM (solid shape): outline of 170 points within 33.69,2.84 43.54,9.63
P3V3_BIC on GND (solid shape): 37.36,14.91 37.36,13 40.41,9.95 40.41,6.94 39.88,6.41 39.53,6.41 39.39,6.56 39.39,8.08 38.37,9.1 38.37,10.37 37.63,11.11 35.85,11.11 35.58,11.38 35.58,14.65 36.36,15.43 36.84,15.43
P3V3_BIC on VCC (solid shape): outline of 815 points within 11.58,1.02 61.48,40.68
P3V3_BT on TOP (solid shape): 29.19,2.29 29.95,2.29 30.06,2.18 30.06,1.47 29.95,1.37 26.73,1.37 26.65,1.45 26.65,2.11 27.03,2.49 28.99,2.49
P3V3_BT on BOTTOM (solid shape): 28.76,2.97 28.76,1.27 28.74,1.24 27.54,1.24 27.41,1.37 27.41,2.62 27.82,3.02 28.71,3.02
P3V3_BT on VCC (solid shape): 17.79,30.92 18.42,30.92 18.94,30.4 18.94,28.27 18.31,27.64 18.31,23.83 15.63,21.15 10.8,21.15 7.13,17.48 7.13,16.33 4.2,13.4 3.05,13.4 2.05,12.4 2.05,3.22 2.93,2.35 3.82,2.35 4.21,1.95 4.21,1.22 4.01,1.02 3.19,1.02 3.14,1.02 3.11,1.05 2.85,1.14 2.6,1.05 2.56,1.02 2.52,1.02 2,1.02 1.3,1.3 1.02,2 1.02,4.96 1.02,5.01 1.05,5.05 1.15,5.31 1.05,5.57 1.02,5.61 1.02,5.65 1.02,7.58 1.02,7.63 1.05,7.67 1.15,7.92 1.05,8.18 1.02,8.22 1.02,8.27 1.02,14.16 1.02,14.2 1.05,14.24 1.15,14.5 1.05,14.76 1.02,14.8 1.02,14.85 1.02,15.56 1.05,15.65 1.14,15.68 3.08,15.68 3.54,16.14 3.6,16.15 3.88,16.29 3.96,16.6 3.96,16.61 3.96,31.54 5.24,32.83 15.88,32.83
P3V3_SW on VCC (solid shape): 25.19,34.48 25.64,34.33 26.08,34.48 26.55,34.48 26.94,34.08 26.94,25.19 28.34,23.8 28.34,20.75 29.22,19.88 30.47,19.88 30.49,19.87 30.59,19.86 30.69,19.87 30.71,19.88 31.02,19.88 31.28,20.13 31.63,20.13 32.02,19.73 32.02,18.87 31.76,18.61 28.23,18.61 27.77,19.06 27.77,19.1 27.66,19.32 27.44,19.43 27.4,19.43 27.33,19.51 27.33,23.83 25.93,25.22 25.93,27.51 24.15,29.29 24.15,30.18 24.47,31 24.15,31.82 24.15,34.21 24.42,34.48
P3V3_VOUT on VCC (solid shape): 47.26,37.26 47.26,36.02 46.63,35.38 46.63,29.03 45.34,27.75 41.82,27.75 41.55,28.02 41.55,28.09 41.55,28.11 41.56,28.19 41.55,28.28 41.55,28.29 41.55,28.75 41.69,28.89 44.23,28.89 45.49,30.15 45.49,37.13 45.76,37.4 47.12,37.4
P5V_MB on TOP (solid shape): 57.77,9.96 57.77,5.28 56.24,3.76 56.24,1.37 56.01,1.14 54.95,1.14 54.85,1.24 54.85,1.55 55.33,2.03 55.33,2.8 55.62,3.09 55.62,4.19 56.45,5.03 56.45,10.57 56.49,10.66 56.58,10.69 57.03,10.69
P5V_MB on TOP (solid shape): 33.71,6.43 33.71,5.92 33.78,5.85 33.78,5.84 34.49,5.84 34.54,5.89 34.69,5.89 35.1,6.3 35.9,6.3 35.95,6.25 35.95,4.19 35.97,4.16 35.97,4.11 36.48,3.61 36.48,2.69 36.48,2.46 36.36,2.34 33.26,2.34 33.08,2.51 33.08,6.45 33.1,6.48 33.66,6.48
P5V_MB on BOTTOM (solid shape): 28.04,27.35 28.06,27.35 28.14,27.28 28.14,25.73 27.94,25.54 25.08,25.54 24.93,25.68 24.93,27.8 25.13,27.99 27.4,27.99
P5V_MB on BOTTOM (solid shape): 36.1,1.85 43.85,1.85 44.7,2.7 45.56,2.7 46.34,1.93 55.91,1.93 56.07,1.78 56.07,0.71 55.91,0.56 33.61,0.56 33,1.17 33,3.51 33.21,3.71 34.25,3.71
P5V_MB on BOTTOM (solid shape): 55.89,17.86 55.89,17.44 56.32,17.01 56.32,15.52 56.32,15.52 56.45,15.39 58.61,15.39 58.7,15.36 58.73,15.27 58.73,14.73 58.71,14.71 56.52,14.71 56.35,14.53 56.35,14.51 56.29,14.51 56.29,13.49 56.35,13.43 56.35,12.17 56.45,12.06 56.45,12.05 56.46,12.05 57.26,11.25 57.26,10.83 57.25,10.78 57.22,10.74 57.16,10.67 57.16,9.07 57.03,8.94 56.91,8.94 56.83,8.96 56.76,8.97 56.14,8.97 55.71,9.4 55.71,11.79 55.19,12.3 55.16,12.39 55.19,12.48 55.23,12.51 55.23,17.05 54.95,17.33 54.95,17.91 55.2,18.16 55.59,18.16
P5V_MB on GND (solid shape): 36.98,16.18 36.98,15.95 36.84,15.81 36.2,15.81 35.2,14.81 35.2,11.22 35.58,10.84 35.58,5.29 34.66,4.37 34.56,4.27 34.56,2.75 34.3,2.48 33.44,2.48 33.17,2.75 33.17,3.73 33.8,4.37 33.8,15.29 34.71,16.19 36.96,16.19
P5V_MB on GND (solid shape): 61.99,10.68 61.99,2 61.55,0.95 60.5,0.51 54.69,0.51 54.6,0.55 54.57,0.64 54.57,1.58 54.58,1.63 54.61,1.67 54.67,1.72 55.13,2.21 55.86,2.94 55.86,4.06 56.73,4.92 56.73,10.51 57.09,10.87 61.8,10.87
P5V_MB on VCC (solid shape): outline of 144 points within 2.43,1.02 34.56,40.11
P5V_MB_FUSE on BOTTOM (solid shape): 36.18,29.84 36.18,27.49 35.91,27.22 32.03,27.22 31.96,27.15 31.49,27.15 29.87,25.54 28.97,25.54 28.83,25.67 28.83,28.12 28.83,28.14 28.84,28.17 28.86,28.2 28.88,28.22 28.93,28.25 28.99,28.29 29.05,28.34 29.1,28.4 29.15,28.46 29.19,28.53 29.22,28.6 29.25,28.67 29.26,28.75 29.27,28.82 29.27,28.87 30.3,28.87 30.3,28.79 30.31,28.74 30.31,28.14 30.93,28.14 30.97,28.14 31.04,28.14 31.1,28.14 31.14,28.14 32.93,28.14 32.97,28.14 33.04,28.14 33.1,28.14 33.14,28.14 33.76,28.14 33.76,28.76 33.77,28.8 33.77,28.87 33.77,28.94 33.76,28.98 33.76,29.62 30.31,29.62 30.31,29 30.3,28.95 30.3,28.87 29.27,28.87 29.27,28.9 29.27,28.98 29.25,29.05 29.23,29.13 29.2,29.2 29.16,29.27 29.12,29.33 29.09,29.36 29.09,30.02 29.68,30.61 35.42,30.61
P5V_USB on BOTTOM (solid shape): 50.17,38.1 50.26,38.06 50.3,37.97 50.3,36.91 50.09,36.7 47.77,36.7 46.79,35.72 46.79,29.05 46.16,28.42 44.14,28.42 43.91,28.66 43.89,28.66 43.7,28.85 41.97,28.85 41.61,28.5 41.61,28.46 41.6,28.43 41.55,28.31 41.54,28.19 41.54,28.12 41.38,27.97 41.05,27.97 40.93,28.09 40.93,28.63 41.49,29.18 41.49,29.64 41.51,29.67 43.75,29.67 43.95,29.46 46.03,29.46 46.16,29.59 46.16,30.24 46.16,34.79 46.16,36.42 46.27,36.62 46.51,36.65 46.91,36.73 47,37.13 47.04,37.36 47.24,37.46 49.16,37.46 49.8,38.1
P5V_USB on GND (solid shape): 41.74,28.47 41.74,28.42 41.67,28.21 41.72,27.99 41.74,27.96 41.74,27.41 40.62,26.29 37.82,26.29 32.74,21.21 30.59,21.21 30.06,20.68 30.06,17.93 31.83,16.15 31.83,6.96 31.73,6.86 31.18,6.86 30.82,7.22 30.82,15.98 29.55,17.25 29.55,20.98 30.29,21.72 32.32,21.72 37.65,27.05 37.88,27.05 37.94,27.03 37.98,27.05 38.04,27.05 38.08,27.09 39.83,27.88 40.24,28.31 40.9,28.57 41.63,28.57
VBAT on TOP (solid shape): 28.02,18.67 28.02,18.6 28.03,18.6 28.45,18.18 28.45,15.38 28.32,15.24 28.32,13.95 28.3,13.93 28.11,13.93 27.87,14.17 27.87,14.63 27.28,15.22 27.28,16.23 27.11,16.41 27.11,18.95 27.36,19.2 27.49,19.2
VBAT on TOP (solid shape): 25.4,9.94 25.4,9.25 25.66,9.25 25.69,9.22 25.69,9.04 26.09,8.64 26.29,8.64 26.51,8.41 26.52,8.38 26.59,8.25 26.72,8.15 26.78,8.12 27.08,7.82 27.1,7.82 27.25,7.68 27.26,7.64 27.27,7.58 27.3,7.53 27.32,7.5 27.32,7.14 27.43,7.14 27.46,7.12 29.12,7.12 29.29,7.29 29.29,7.62 29.34,7.67 29.88,7.67 29.9,7.65 29.9,6.88 29.8,6.78 29.55,6.78 29.5,6.73 29.43,6.73 29.43,6.66 29.31,6.54 27.37,6.54 26.21,7.7 26.11,7.7 26.11,7.71 25.05,7.71 24.77,8 24.32,9.08 24.32,9.71 24.69,10.08 25.26,10.08
VBAT on GND (solid shape): 29.48,24.18 29.48,23.83 27.71,22.05 27.71,18.62 27.56,18.48 27.21,18.48 26.94,18.75 26.94,22.15 28.99,24.19 29.47,24.19
VBAT on VCC (solid shape): 20.46,18.18 20.48,18.15 20.83,17.91 21.18,18.15 21.19,18.18 21.26,18.22 28.07,18.22 28.34,17.96 28.34,15.19 27.82,14.67 18.58,14.67 18.31,14.94 18.31,16.43 20.1,18.22 20.4,18.22
NMOS_D on TOP (solid shape): 14.18,9.07 14.18,8.41 14.16,8.38 13.77,8.38 13.69,8.42 13.65,8.5 13.3,8.86 12.9,8.57 12.89,8.54 12.73,8.38 12.28,8.38 12.23,8.43 12.23,9.06 12.32,9.14 14.1,9.14
S3_A2 on GND (solid shape): 22.37,13.89 22.37,11.13 20.59,9.35 20.59,5.16 20.58,5.14 19.72,5.14 19.71,5.16 19.71,9.7 21.74,11.73 21.74,12.83 21.75,12.86 21.64,13.45 21.05,13.53 20.99,13.53 20.85,13.67 20.85,14.02 20.99,14.16 22.1,14.16
N17920453 on TOP (solid shape): 57.03,38.89 57.28,38.79 57.55,38.74 57.64,38.7 57.67,38.61 58,38.2 58.42,38.52 58.51,38.67 58.67,38.73 60.99,38.73 61.08,38.69 61.12,38.6 61.12,35.51 60.87,35.26 59.27,35.26 58.39,36.13 58.02,36.13 57.93,36.17 57.89,36.26 57.51,36.63 57.13,36.26 57.13,36.21 57.06,36.13 53.21,36.13 51.82,37.52 51.82,38.79 51.93,38.89
N17920453 on BOTTOM (solid shape): 61.37,38.94 61.46,38.9 61.5,38.81 61.5,34.44 61.46,34.35 61.37,34.32 59.56,34.32 59.32,34.56 59.32,38.76 59.49,38.94
N18364020 on TOP (solid shape): 18.85,11.48 18.85,9.8 18.27,9.22 18.27,6.96 18.22,6.91 16.64,6.91 16.59,6.96 16.59,9.12 16.75,9.27 16.8,9.27 18.63,11.1 18.63,11.48 18.68,11.53 18.8,11.53
N18364026 on TOP (solid shape): 19.87,11.53 19.87,10.46 20.68,9.65 21.17,9.65 21.55,9.27 21.55,7.06 21.43,6.94 20.04,6.94 19.87,7.11 19.87,9.22 19.62,9.47 19.62,11.53 19.64,11.56 19.85,11.56

Small or netless copper shapes (teardrops, artwork), in the pictures only: 5 on TOP, 2 on BOTTOM

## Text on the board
Ref Des/Silkscreen Bottom: USB | DB_COM | USB_MB | MCU_DB_COM | JTAG | A | LCD_BL_CONN
Ref Des/Silkscreen Top: BAT_STATUS | BT_SW | UART_SEL | RST_BTN | PWR_BTN | MCU_HB | BT_LED | LCD_5_DIR_SW | +
User.45: DETAIL E | DETAIL B | DETAIL D | DETAIL C | DETAIL A | DETAIL F | FIGURE | SIZE | 10.0 | 35.0 | 34.0 | 36.0 | 42.0 | 46.0 | 56.0 | 44.0x28.0 | 48.0x20.0 | 56.0x32.0 | 63.0x20.0 | 73.0x32.0 | 95.0x20.0 | DRILL CHART: TOP to BOTTOM | ALL UNITS ARE IN MILS | TOLERANCE | +3.0/-3.0 | +2.0/-2.0 | +4.0/-4.0 | +1.96/-1.96 | PLATED | NON-PLATED | QTY | 69 | 308 | 4 | 1 | 2
